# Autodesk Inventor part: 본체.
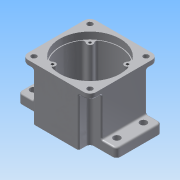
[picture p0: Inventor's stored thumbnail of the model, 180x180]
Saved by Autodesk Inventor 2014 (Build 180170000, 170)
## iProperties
Created: 2015-06
Part Number: 본체.
Material: 알루미늄 6061
Document SubType Name: Modeling
Designer: AMC
Density: 2.71 g/cm^3
Appearance: 알루미늄 - 평지
Mass: 704.954 g
Surface Area: 674.788 cm^2
Volume: 260.131 cm^3
Author: AMC
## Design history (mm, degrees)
sketch "스케치1"
  geometry: L1 (0, 0)-(30, 0); L2 (30, 0)-(30, 15); L3 (30, 15)-(65, 15); L4 (65, 15)-(65, 75); L5 (65, 75)-(30, 75); L6 (30, 75)-(30, 90); L7 (30, 90)-(0, 90); L8 (0, 90)-(0, 0); L9 (0, 0)-(-30, 0); L10 (-30, 0)-(-30, 15); L11 (-30, 15)-(-65, 15); L12 (-65, 15)-(-65, 75); L13 (-65, 75)-(-30, 75); L14 (-30, 75)-(-30, 90); L15 (-30, 90)-(0, 90)
  constraints: 30 end point, 6 symmetric about line, 5 parallel, 1 collinear, 1 horizontal, 1 perpendicular
  dimensions: "d0" = 130 diameter of L4 L8; "d1" = 60 diameter of L6 L8; "d2" = 60 diameter of L2 L8; "d3" = 60 distance between parallel lines of L5 L3; "d4" = 90 distance between parallel lines of L1 L7; "d5" = 15 distance between parallel lines of L1 L3
extrude "돌출1" new body sketch "스케치1" distance "d6" = 12; taper "d7" = 0 deg
sketch "스케치2"
  geometry: L1 (30, 90)-(-30, 90) reference; L2 (-30, 90)-(-30, 75) reference; L3 (-30, 75)-(-65, 75) reference; L4 (-65, 15)-(-30, 15) reference; L5 (-30, 15)-(-30, 0) reference; L6 (-30, 0)-(30, 0) reference; L7 (30, 0)-(30, 15) reference; L8 (30, 15)-(65, 15) reference; L9 (65, 75)-(30, 75) reference; L10 (30, 75)-(30, 90) reference; L11 (-45, 75)-(-45, 15); L12 (45, 75)-(45, 15); 1 further point
  constraints: 4 end point, 4 point on line, 2 perpendicular
  dimensions: "d8" = 45 distance from line of L12 point (0, 0); "d9" = 90 distance between parallel lines of L11 L12
extrude "돌출2" join sketch "스케치2" distance "d10" = 51; taper "d11" = 0 deg
sketch "스케치3"
  geometry: L1 (-45, 75)-(-45, 15) reference; L2 (-45, 15)-(-30, 15) reference; L3 (30, 0)-(30, 15) reference; L4 (45, 75)-(30, 75) reference; L5 (-45, 90)-(45, 90); L6 (45, 90)-(45, 0); L7 (45, 0)-(-45, 0); L8 (-45, 0)-(-45, 90); 1 further point
  constraints: 8 end point, 2 parallel, 1 horizontal, 1 perpendicular, 1 point on line
  dimensions: "d12" = 15 distance between parallel lines of L2 L7; "d13" = 15 distance between parallel lines of L4 L5; "d14" = 15 distance between parallel lines of L3 L6
extrude "돌출3" join sketch "스케치3" distance "d15" = 7; taper "d16" = 0 deg
sketch "스케치4"
  geometry: L1 (45, 0)-(45, 90) reference; C1 r 40 at (0, 45); 2 further points
  constraints: 1 centre point, 1 midpoint
  dimensions: "d17" = 80 diameter of C1; "d18" = 0 horizontal distance of point (0, 0) C1.centre; "d19" = 0 vertical distance of point (45, 45) C1.centre
extrude "돌출4" cut sketch "스케치4" distance "d20" = 9; taper "d21" = 0 deg
sketch "스케치5"
  geometry: L1 (0, 0)-(24.749, 24.749); L2 (0, 0)-(35, 0); L3 (21.92, 27.577)-(24.603, 30.26); L4 (27.577, 21.92)-(30.26, 24.603); C1 r 40 at (0, 0) reference; A1 r 39 centre (0, 0) between (24.603, 30.26) and (30.26, 24.603); A2 r 4 centre (24.749, 24.749) between (21.92, 27.577) and (27.577, 21.92); 1 further point
  constraints: 8 end point, 4 point on circle, 2 centre point, 2 coincident, 2 parallel, 2 tangent, 1 equal length, 1 horizontal
  dimensions: "d22" = 78 diameter of A1; "d23" = 35 distance of L1.start L1.end; "d24" = 45 deg angle of L2 L1; "d25" = 8 diameter of A2
extrude "돌출5" cut sketch "스케치5" distance "d26" = 52; taper "d27" = 0 deg
extrude "돌출6" join sketch "스케치5" distance "d28" = 52; taper "d29" = 0 deg
fillet "모깎기1" dims "d30" = 3.5
hole "구멍1" diameter "d33" = 3.459; stored, may be unused: countersink angle "d37" = 90 deg, drill point angle "d39" = 118 deg; dims "d31" = 10, "d32" = 10, "d34" = 12, "d35" = 4, "d36" = 2, "d38" = 15
sketch "스케치6"
  geometry: A1 r 39 centre (0, 0) between (-32.777, 21.134) and (-32.777, -21.134) reference; A2 r 39 centre (0, 0) between (-21.134, -32.777) and (21.134, -32.777) reference; A3 r 20.5 centre (0, 11) between (7.402, -8.117) and (-7.402, -8.117); A4 r 14 centre (0, -20) between (-7.402, -8.117) and (7.402, -8.117); 1 further point
  constraints: 4 point on circle, 2 centre point
  dimensions: "d43" = 41 diameter of A3; "d44" = 0 horizontal distance of A3.centre A1.centre; "d45" = 11 distance of A2.centre A3.centre; "d46" = 28 diameter of A4; "d47" = 0 horizontal distance of A1.centre A4.centre; "d48" = 20 distance of A1.centre A4.centre
extrude "돌출7" join sketch "스케치6" distance "d49" = 7; taper "d50" = 0 deg
sketch "스케치7"
  geometry: L1 (65, 75)-(65, 15) reference; C1 r 25 at (0, 56); 2 further points
  constraints: 1 centre point, 1 midpoint
  dimensions: "d51" = 50 diameter of C1; "d52" = 0 horizontal distance of point (0, 0) C1.centre; "d53" = 11 vertical distance of point (65, 45) C1.centre
extrude "돌출8" join sketch "스케치7" distance "d54" = 7; taper "d55" = 0 deg
sketch "스케치8"
  geometry: L1 (5, 70)-(5, 61) reference; L2 (5, 61)-(6, 61) reference; L3 (6, 61)-(6, 9) reference; L4 (6, 9)-(11, 9) reference; L5 (11, 9)-(11, 16) reference; L6 (11, 16)-(76.5, 16) reference; L7 (76.5, 16)-(76.5, 9) reference; L8 (76.5, 9)-(84, 9) reference; L9 (84, 9)-(84, 61) reference; L10 (84, 61)-(85, 61) reference; L11 (85, 61)-(85, 70) reference; L12 (85, 70)-(90, 70) reference; L13 (90, 70)-(90, 0) reference; L14 (90, 0)-(81, 0) reference; L15 (81, 0)-(81, -7) reference; L16 (81, -7)-(31, -7) reference; L17 (31, -7)-(31, 0) reference; L18 (31, 0)-(0, 0) reference; L19 (0, 0)-(0, 70) reference; L20 (0, 70)-(5, 70) reference; L21 (56, -7)-(56, 16); L22 (72, -7)-(72, 1); L23 (72, 1)-(68.5, 1); L24 (68.5, 1)-(68.5, 6); L25 (68.5, 6)-(73.5, 6); L26 (73.5, 6)-(73.5, 16); L27 (25, 16)-(25, 8); L28 (25, 8)-(34.5, 8); L29 (34.5, 8)-(34.5, 9); L30 (34.5, 9)-(36, 9); L31 (36, 9)-(36, 16)
  constraints: 22 end point, 6 parallel, 5 perpendicular, 5 point on line, 1 midpoint
  dimensions: "d56" = 35 diameter of L26 L21; "d57" = 32 diameter of L22 L21; "d58" = 25 diameter of L24 L21; "d59" = 8 distance between parallel lines of L16 L23; "d60" = 5 distance between parallel lines of L25 L23; "d61" = 14 distance from line of L27.start L5; "d62" = 22 diameter of L31 L27; "d63" = 19 diameter of L29 L27; "d64" = 1 distance between parallel lines of L30 L28; "d65" = 7 distance between parallel lines of L6 L30
  node "절단 모서리 투영1"
revolve "회전1" stored, may be unused: angle "d66" = 90 deg
revolve "회전2" stored, may be unused: angle "d67" = 90 deg
fillet "모깎기3" dims "d76" = 8, "d77" = 2, "d116" = 3
fillet "모깎기4" dims "d78" = 2, "d79" = 5
fillet "모깎기5" dims "d80" = 2
fillet "모깎기6" dims "d81" = 2
fillet "모깎기7" dims "d82" = 0.3
fillet "모깎기8" dims "d83" = 1
chamfer "모따기1" distance "d84" = 1; stored, may be unused: second distance "d85" = 2, angle "d86" = 45 deg
sketch "스케치10"
  geometry: L1 (28, 0)-(-28, 0) reference; C1 r 27 at (0, 56) reference; 2 further points
  constraints: 1 other
  dimensions: "d87" = 0 horizontal distance of C1.centre point (0, 15); "d88" = 15 distance from line of L1 point (0, 15)
feature "엠보싱1" sketch "스케치10" dims "d0" = 130, "d1" = 60, "d2" = 60, "d3" = 60, "d4" = 90, "d5" = 15, "d89" = 0.5, "d90" = 0
fillet "모깎기10" dims "d92" = 5
sketch "스케치11"
  geometry: L1 (-63, 20)-(-63, 70) reference; L2 (-30, 2)-(-30, 10) reference; L3 (-35, 15)-(-43.536, 15) reference; L4 (-60, 17)-(-47, 17) reference; L5 (-63, 70)-(-63, 20) reference; L6 (-47, 73)-(-60, 73) reference; L7 (-47, 73)-(-47, 17) reference; L8 (28, 0)-(-28, 0) reference; L9 (30, 10)-(30, 2) reference; L10 (43.536, 15)-(35, 15) reference; L11 (47, 17)-(47, 73) reference; L12 (60, 73)-(47, 73) reference; L13 (63, 20)-(63, 70) reference; L14 (47, 17)-(60, 17) reference; L15 (-43.536, 75)-(-35, 75) reference; L16 (-30, 80)-(-30, 88) reference; L17 (-28, 90)-(28, 90) reference; L18 (30, 88)-(30, 80) reference; L19 (35, 75)-(43.536, 75) reference; C1 r 11 at (0, 25) reference; C2 r 17.5 at (0, 56) reference; A1 r 2 centre (-28, 2) between (-30, 2) and (-28, 0) reference; A2 r 5 centre (-35, 10) between (-30, 10) and (-35, 15) reference; A3 r 3 centre (-60, 20) between (-63, 20) and (-60, 17) reference; A4 r 3 centre (-60, 70) between (-60, 73) and (-63, 70) reference; A5 r 2 centre (28, 2) between (28, 0) and (30, 2) reference; A6 r 5 centre (35, 10) between (35, 15) and (30, 10) reference; A7 r 3 centre (60, 70) between (63, 70) and (60, 73) reference; A8 r 3 centre (60, 20) between (60, 17) and (63, 20) reference; A9 r 5 centre (-35, 80) between (-35, 75) and (-30, 80) reference; A10 r 2 centre (-28, 88) between (-28, 90) and (-30, 88) reference; A11 r 2 centre (28, 88) between (30, 88) and (28, 90) reference; A12 r 5 centre (35, 80) between (30, 80) and (35, 75) reference; A13 r 3 centre (12.742, 36.254) between (11.115, 38.775) and (10.493, 34.268) reference; A14 r 14 centre (0, 25) between (-10.493, 34.268) and (10.493, 34.268) reference; A15 r 3 centre (-12.742, 36.254) between (-10.493, 34.268) and (-11.115, 38.775) reference; A16 r 20.5 centre (0, 56) between (11.115, 38.775) and (-11.115, 38.775) reference; A17 r 3.5 centre (19.238, 15.164) between (21.134, 12.223) and (21.809, 17.538) reference; A18 r 3.5 centre (29.836, 25.762) between (27.462, 23.191) and (32.777, 23.866) reference; A19 r 39 centre (0, 45) between (32.777, 23.866) and (32.777, 66.134) reference; A20 r 3.5 centre (29.836, 64.238) between (32.777, 66.134) and (27.462, 66.809) reference; A21 r 3.5 centre (19.238, 74.836) between (21.809, 72.462) and (21.134, 77.777) reference; A22 r 39 centre (0, 45) between (21.134, 77.777) and (-21.134, 77.777) reference; A23 r 3.5 centre (-19.238, 74.836) between (-21.134, 77.777) and (-21.809, 72.462) reference; A24 r 3.5 centre (-29.836, 64.238) between (-27.462, 66.809) and (-32.777, 66.134) reference; A25 r 39 centre (0, 45) between (-32.777, 66.134) and (-32.777, 23.866) reference; A26 r 3.5 centre (-29.836, 25.762) between (-32.777, 23.866) and (-27.462, 23.191) reference; A27 r 3.5 centre (-19.238, 15.164) between (-21.809, 17.538) and (-21.134, 12.223) reference; A28 r 39 centre (0, 45) between (-21.134, 12.223) and (21.134, 12.223) reference; A29 r 4 centre (-24.749, 69.749) between (-27.462, 66.809) and (-21.809, 72.462) reference; A30 r 4 centre (-24.749, 20.251) between (-21.809, 17.538) and (-27.462, 23.191) reference; A31 r 4 centre (24.749, 20.251) between (27.462, 23.191) and (21.809, 17.538) reference; A32 r 4 centre (24.749, 69.749) between (21.809, 72.462) and (27.462, 66.809) reference; 3 further points
  constraints: 1 midpoint, 4 other
  dimensions: "d93" = 6 distance from line of L1 point (-57, 62.5); "d94" = 17.5 vertical distance of point (-57, 62.5) point (-47, 45)
hole "구멍3" sketch "스케치11" at (-57, 62.5) diameter "d95" = 9; stored, may be unused: countersink angle "d99" = 90 deg, drill point angle "d101" = 118 deg; dims "d96" = 6, "d97" = 4, "d98" = 2, "d100" = 8
sketch "스케치12"
  geometry: A1 r 8 centre (-37, 82) between (-37, 90) and (-45, 82) reference; A2 r 8 centre (-37, 8) between (-45, 8) and (-37, 0) reference; A3 r 8 centre (37, 8) between (37, 0) and (45, 8) reference; A4 r 8 centre (37, 82) between (45, 82) and (37, 90) reference; 1 further point
hole "구멍4" sketch "스케치12" at (37, 82), (37, 8), (-37, 8), (-37, 82) diameter "d108" = 7; stored, may be unused: countersink angle "d112" = 90 deg, drill point angle "d114" = 118 deg; dims "d109" = 6, "d110" = 4, "d111" = 2, "d113" = 8
fillet "모깎기11" dims "d115" = 2
node "솔리드1"
pattern_circular "원형 패턴1" dims "d41" = 360 deg
pattern_linear "직사각형 패턴1" dims "d104" = 35
node "절단 모서리 투영3"
